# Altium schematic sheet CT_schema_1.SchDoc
size 543 x 488 mm
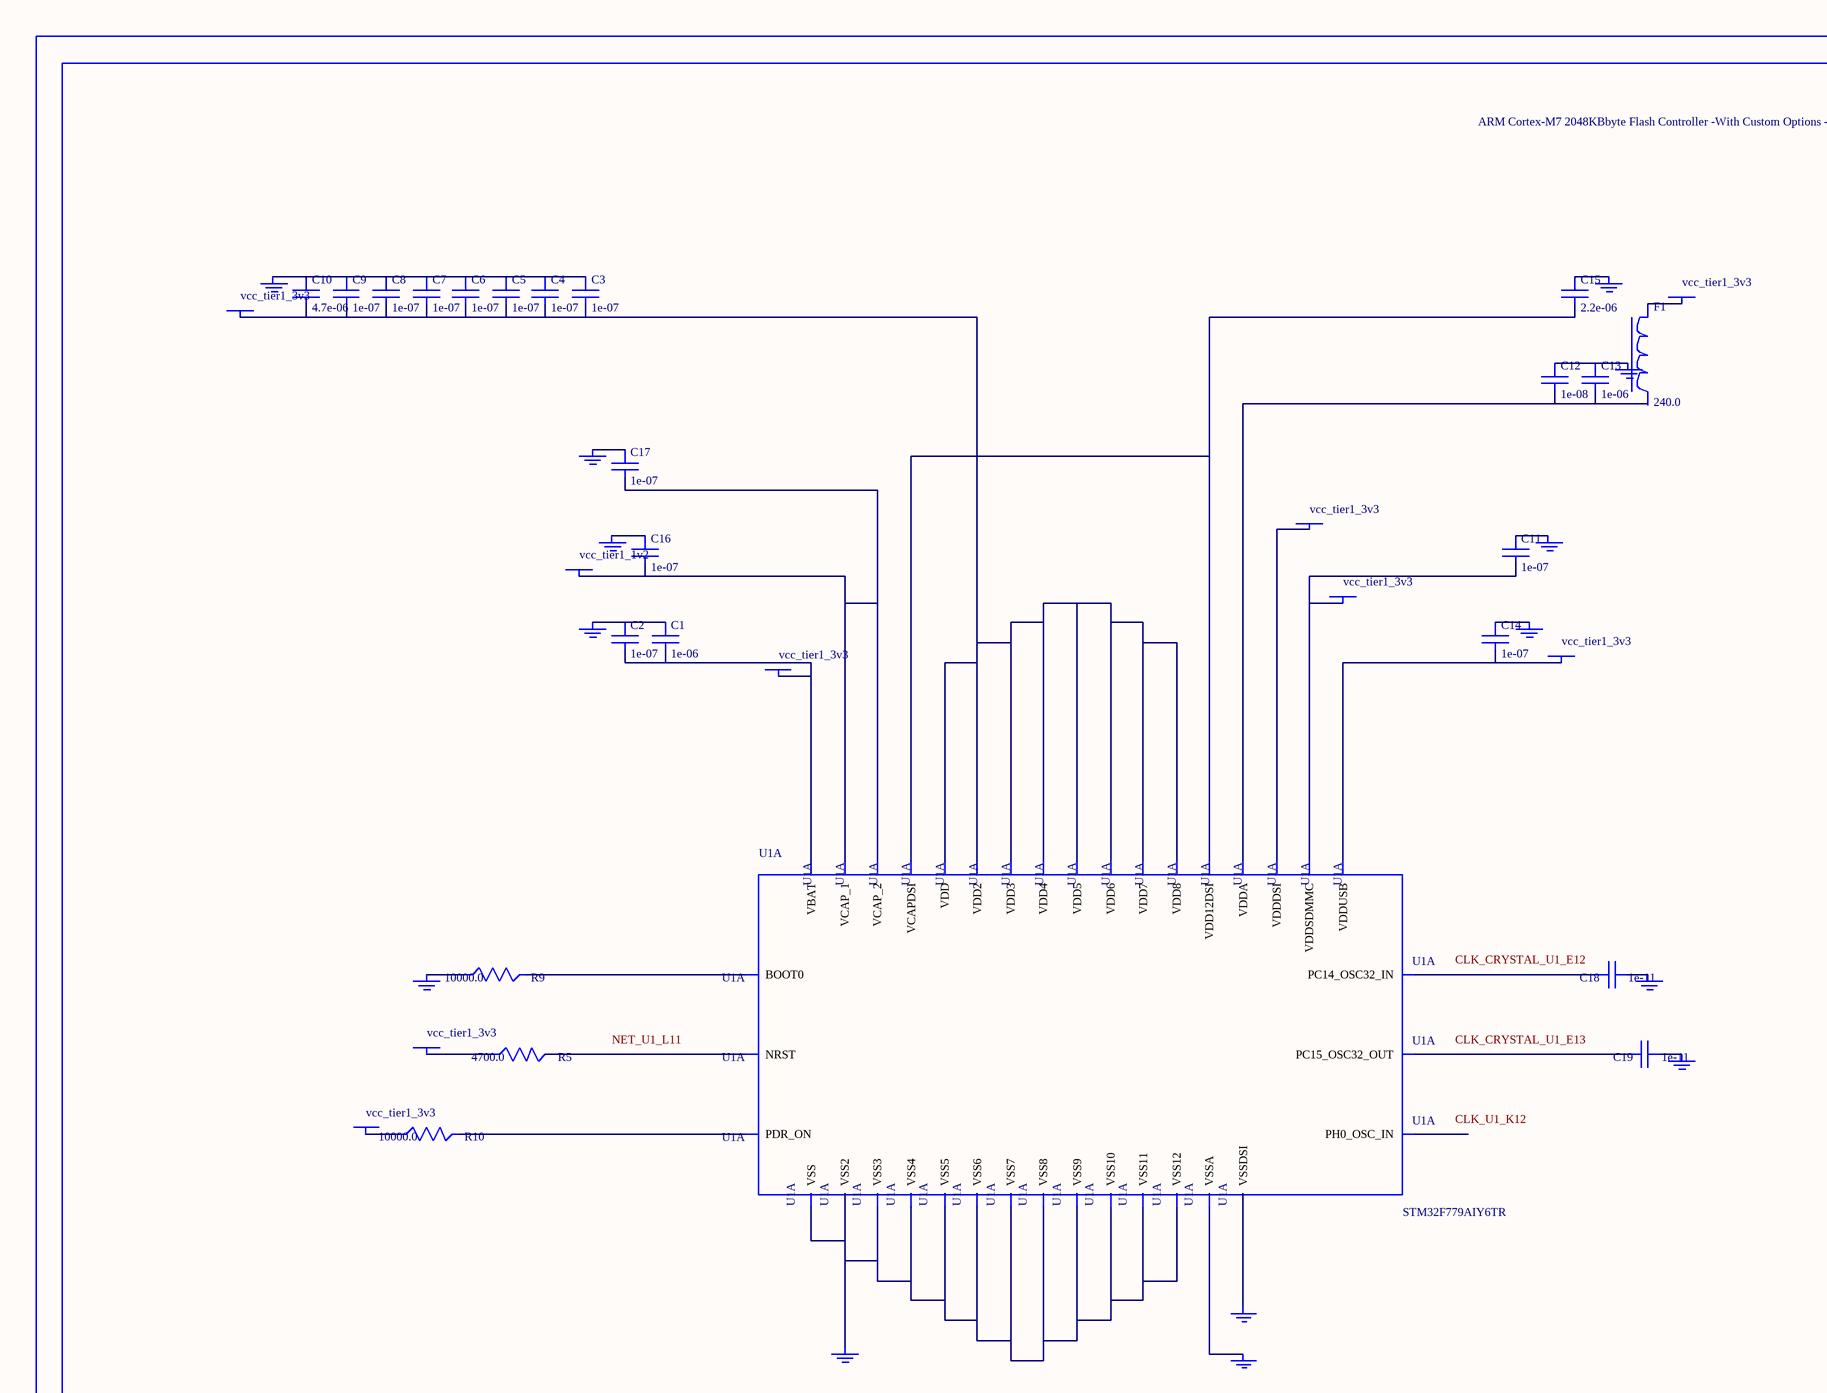
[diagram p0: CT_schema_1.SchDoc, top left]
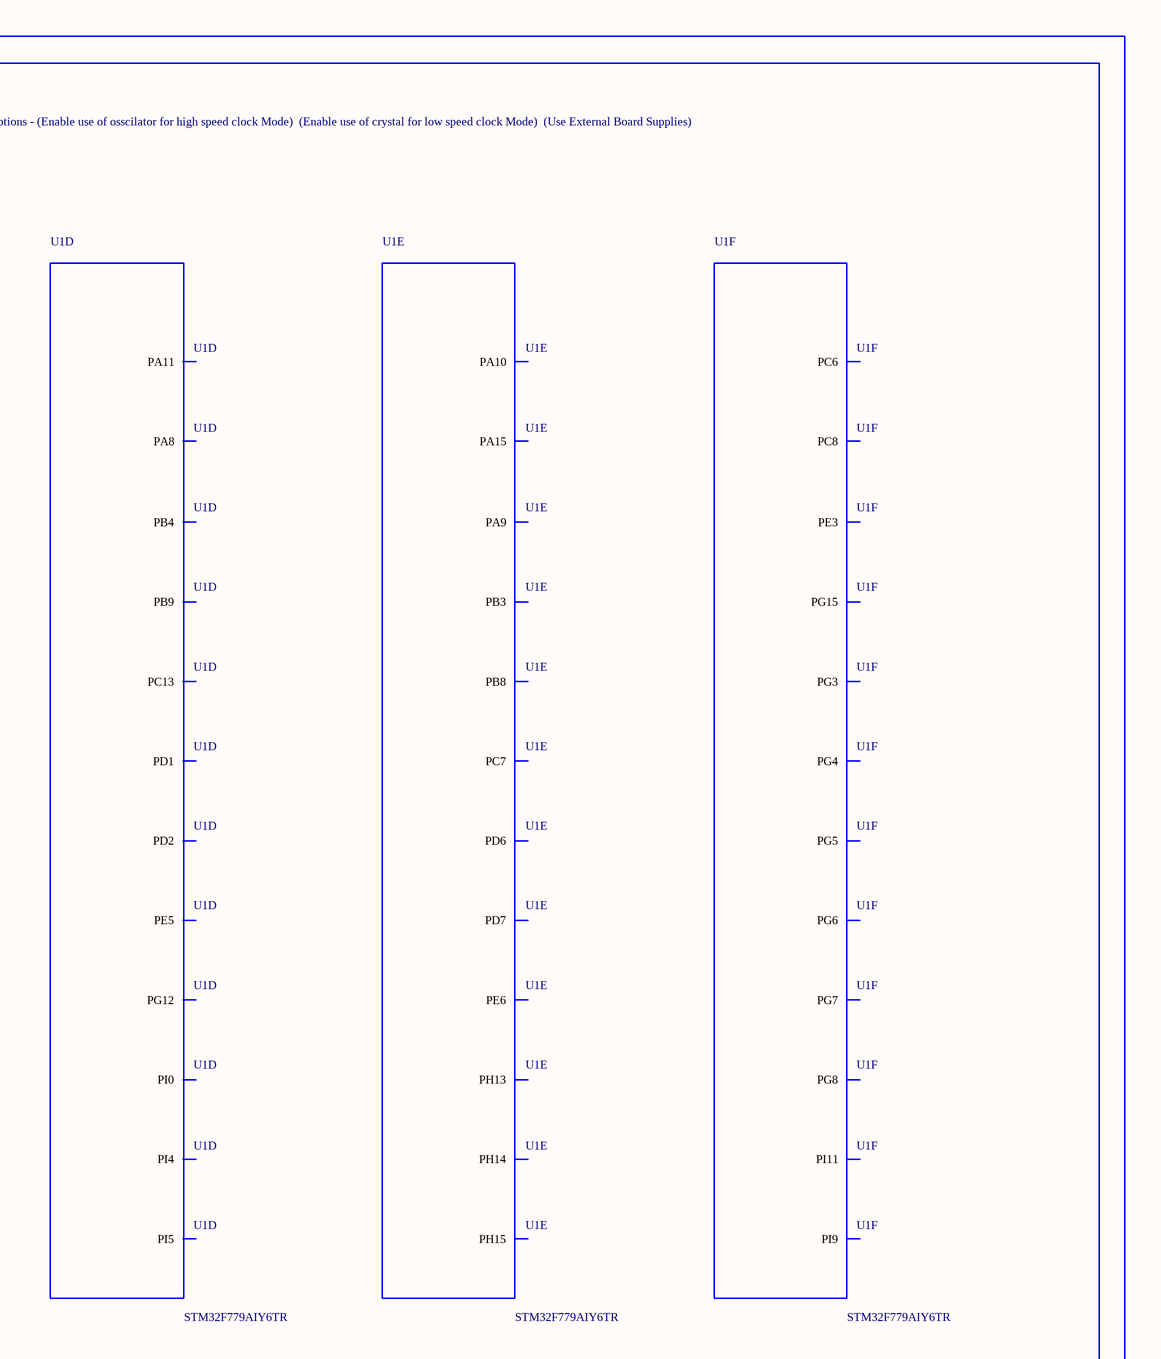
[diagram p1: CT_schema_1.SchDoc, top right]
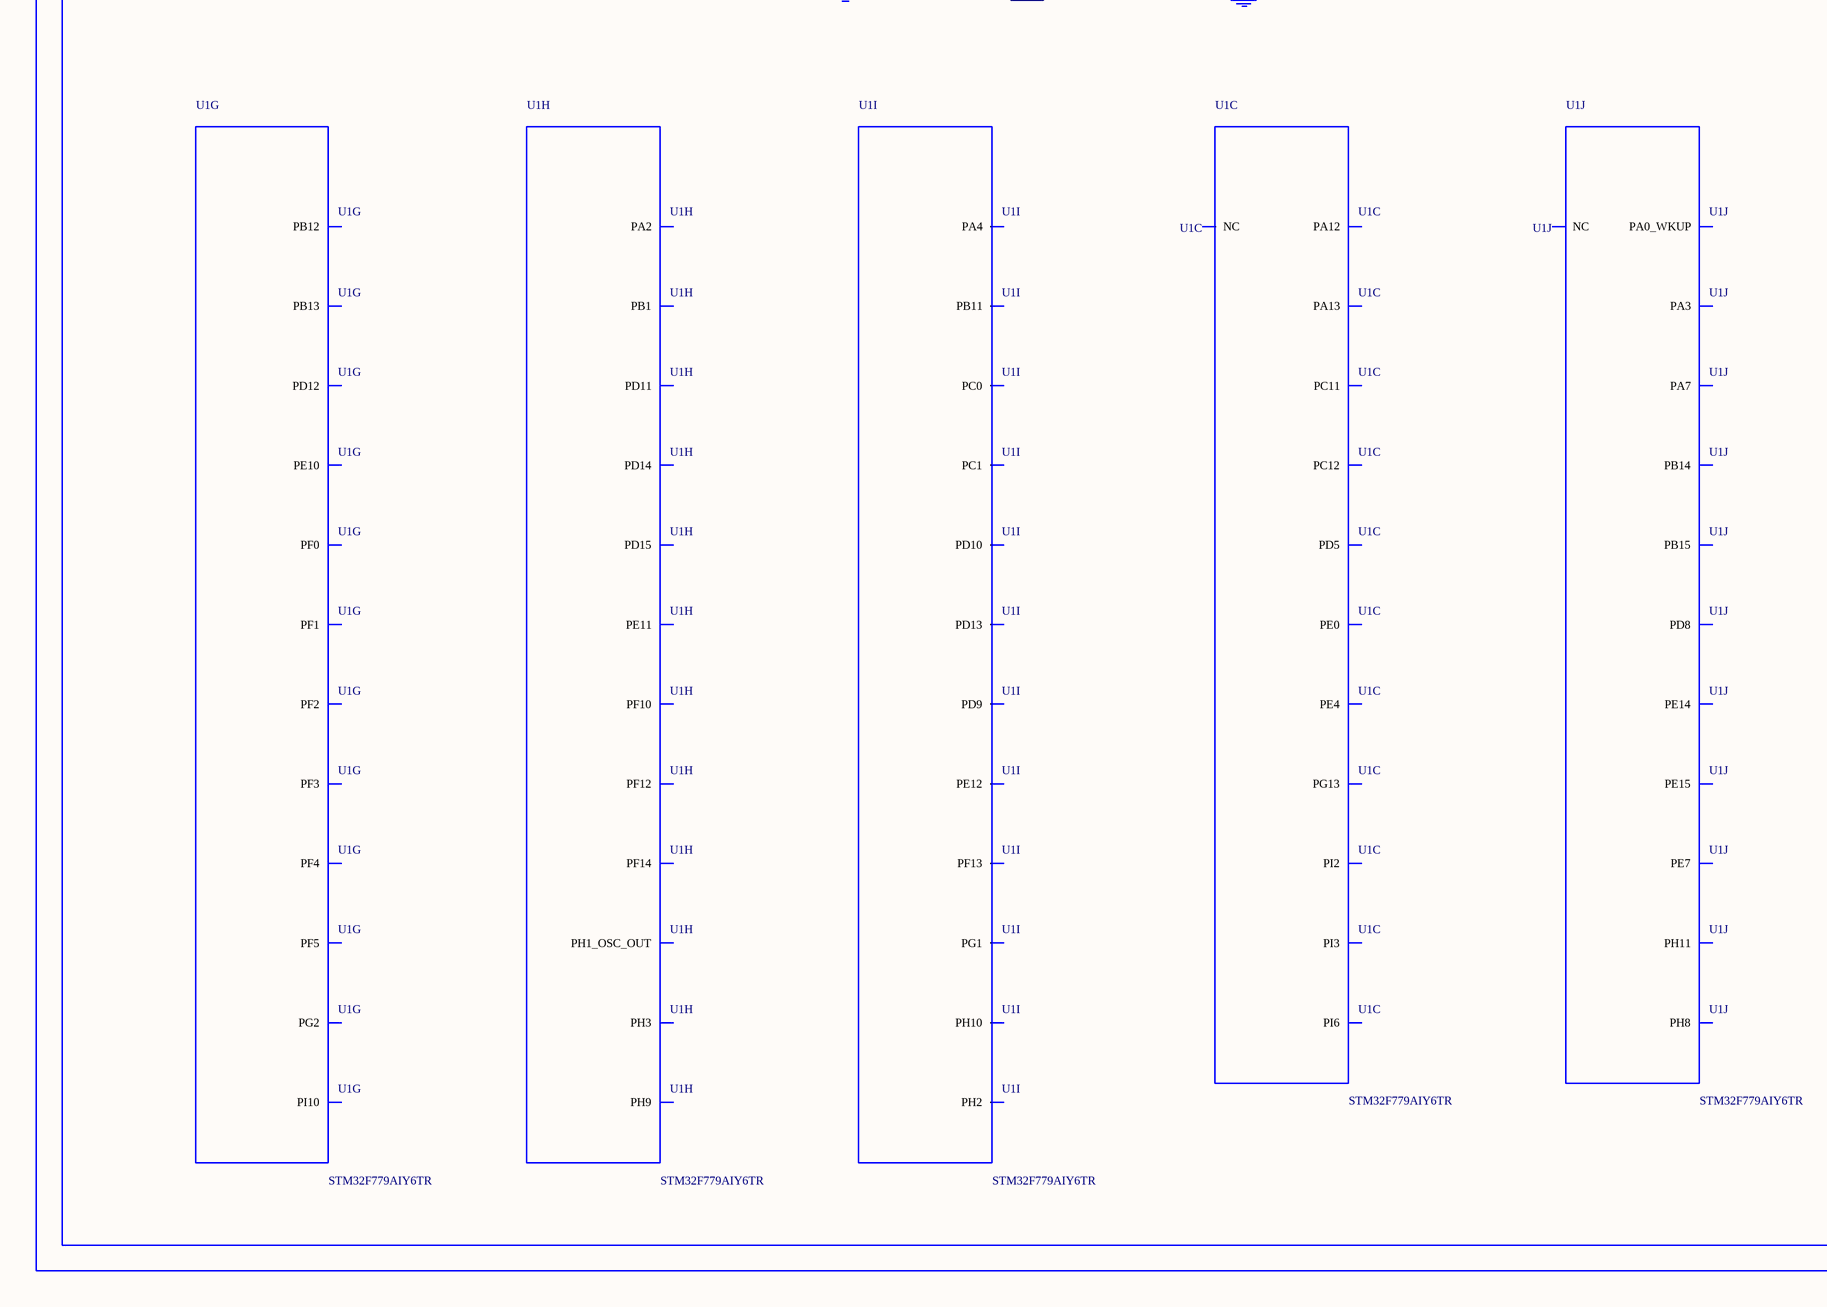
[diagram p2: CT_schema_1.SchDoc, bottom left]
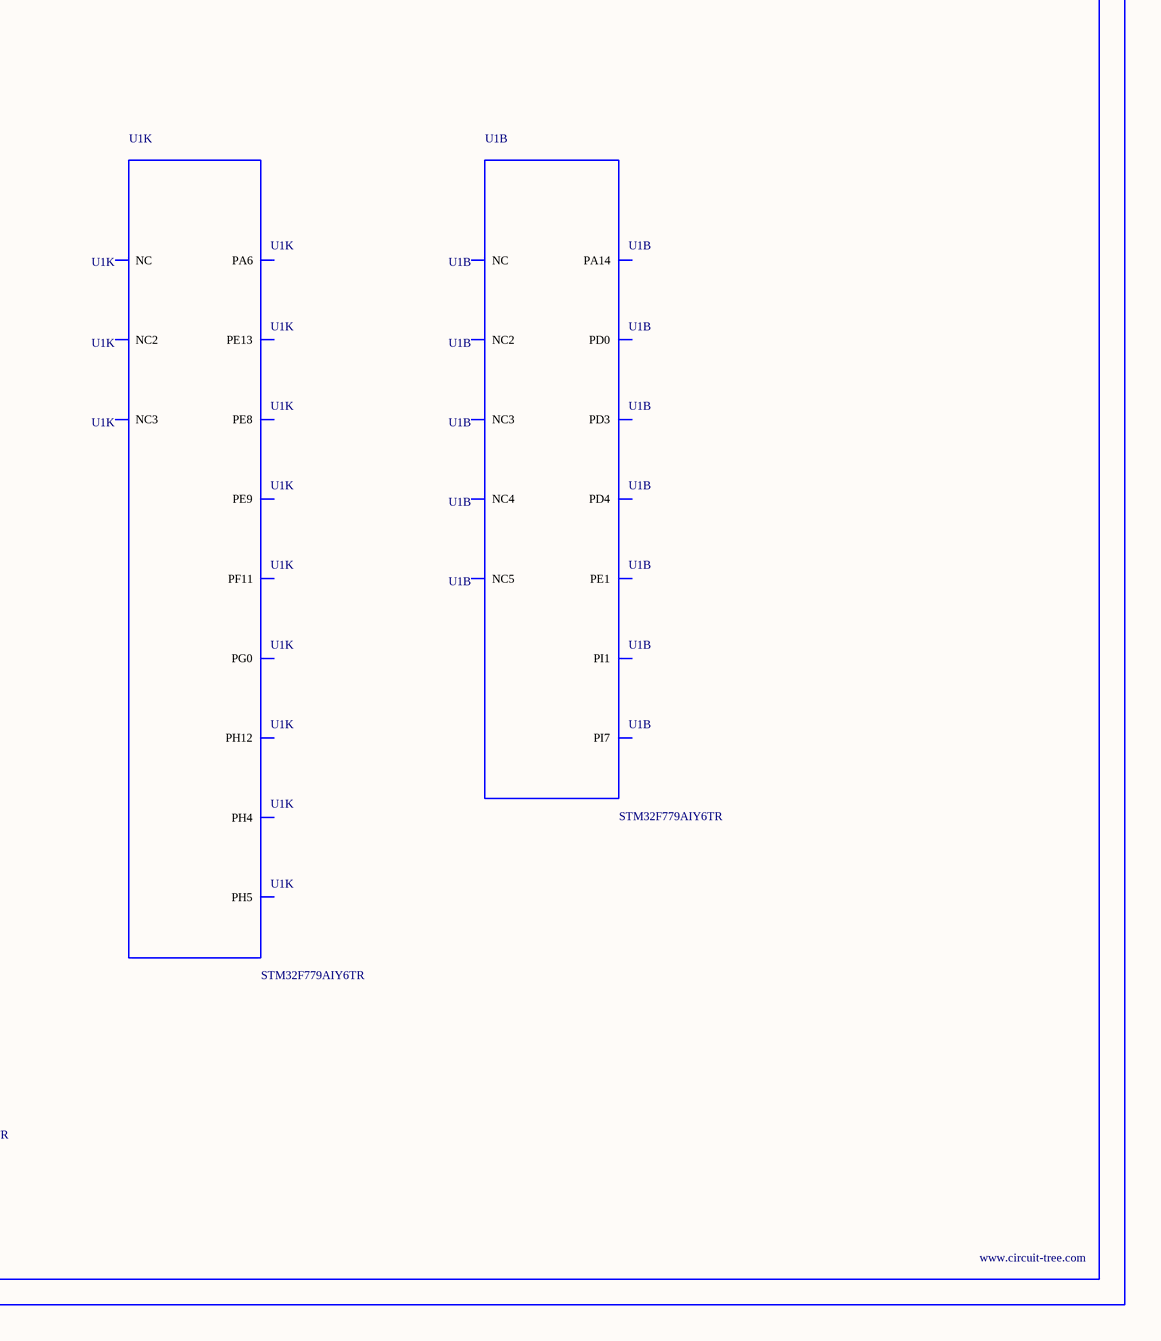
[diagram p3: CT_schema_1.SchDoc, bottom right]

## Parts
BORDER0  (no value)
C1  1e-06  [C0603]
C2  1e-07  [C0603]
C3  1e-07  [C0603]
C4  1e-07  [C0603]
C5  1e-07  [C0603]
C6  1e-07  [C0603]
C7  1e-07  [C0603]
C8  1e-07  [C0603]
C9  1e-07  [C0603]
C10  4.7e-06  [C0603]
C11  1e-07  [C0603]
C12  1e-08  [C0603]
C13  1e-06  [C0603]
C14  1e-07  [C0603]
C15  2.2e-06  [C0603]
C16  1e-07  [C0603]
C17  1e-07  [C0603]
C18  1e-11  [C0402]
C19  1e-11  [C0402]
F1  240.0  [L0603]
GND_INSTANCE_0_0  (no value)
GND_INSTANCE_0_1  (no value)
GND_INSTANCE_0_2  (no value)
GND_INSTANCE_0_3  (no value)
GND_INSTANCE_0_4  (no value)
GND_INSTANCE_0_5  (no value)
GND_INSTANCE_0_6  (no value)
GND_INSTANCE_0_7  (no value)
GND_INSTANCE_0_8  (no value)
GND_INSTANCE_0_9  (no value)
GND_INSTANCE_0_10  (no value)
GND_INSTANCE_0_11  (no value)
GND_INSTANCE_0_12  (no value)
GND_INSTANCE_0_13  (no value)
POWER_INSTANCE_0_0  vcc_tier1_3v3
POWER_INSTANCE_0_1  vcc_tier1_3v3
POWER_INSTANCE_0_2  vcc_tier1_3v3
POWER_INSTANCE_0_3  vcc_tier1_3v3
POWER_INSTANCE_0_4  vcc_tier1_3v3
POWER_INSTANCE_0_5  vcc_tier1_3v3
POWER_INSTANCE_0_6  vcc_tier1_1v2
POWER_INSTANCE_0_7  vcc_tier1_3v3
POWER_INSTANCE_0_8  vcc_tier1_3v3
R5  4700.0  [R0603]
R9  10000.0  [R0603]
R10  10000.0  [R0603]
U1  STM32F779AIY6TR  [WLCSP180]  (parts A,B,C,D,E,F,G,H,I,J,K of 15)

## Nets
NetC1_1: C1.1 C2.1 GND_INSTANCE_0_0.0(GND)
NetC1_2: C1.2 C2.2 POWER_INSTANCE_0_0.0(PWR) U1.C13(VBAT)
NetC3_1: C3.1 C4.1 C5.1 C6.1 C7.1 C8.1 C9.1 C10.1 GND_INSTANCE_0_2.0(GND)
NetC3_2: C3.2 C4.2 C5.2 C6.2 C7.2 C8.2 C9.2 C10.2 POWER_INSTANCE_0_2.0(PWR) U1.B2(VDD2) U1.B8(VDD3) U1.B11(VDD) U1.F12(VDD4) U1.J12(VDD5) U1.K9(VDD6) U1.M8(VDD7) U1.P4(VDD8)
NetC11_1: C11.1 GND_INSTANCE_0_4.0(GND)
NetC11_2: C11.2 POWER_INSTANCE_0_3.0(PWR) U1.A6(VDDSDMMC)
NetC12_1: C12.1 C13.1 GND_INSTANCE_0_1.0(GND)
NetC12_2: C12.2 C13.2 U1.M12(VDDA)
NetC14_1: C14.1 GND_INSTANCE_0_5.0(GND)
NetC14_2: C14.2 POWER_INSTANCE_0_5.0(PWR) U1.F2(VDDUSB)
NetC15_1: C15.1 GND_INSTANCE_0_6.0(GND)
NetC15_2: C15.2 U1.H6(VCAPDSI) U1.J3(VDD12DSI)
NetC16_1: C16.1 GND_INSTANCE_0_7.0(GND)
NetC16_2: C16.2 C17.2 POWER_INSTANCE_0_6.0(PWR) U1.C1(VCAP_2) U1.P5(VCAP_1)
NetC17_1: C17.1 GND_INSTANCE_0_8.0(GND)
NetC18_1: C18.1 GND_INSTANCE_0_9.0(GND)
NetC18_2: C18.2 U1.E12(PC14_OSC32_IN)
NetC19_1: C19.1 GND_INSTANCE_0_10.0(GND)
NetC19_2: C19.2 U1.E13(PC15_OSC32_OUT)
NetF1_1: F1.1 POWER_INSTANCE_0_1.0(PWR)
NetGND_INSTANCE_0_3_0: GND_INSTANCE_0_3.0(GND) R9.1
NetGND_INSTANCE_0_11_0: GND_INSTANCE_0_11.0(GND) U1.M11(VSSA)
NetGND_INSTANCE_0_12_0: GND_INSTANCE_0_12.0(GND) U1.A8(VSS2) U1.A11(VSS) U1.B6(VSS3) U1.C2(VSS4) U1.F1(VSS5) U1.F13(VSS6) U1.J9(VSS8) U1.J13(VSS7) U1.M1(VSS9) U1.N4(VSS10) U1.N5(VSS11) U1.P9(VSS12)
NetGND_INSTANCE_0_13_0: GND_INSTANCE_0_13.0(GND) U1.H5(VSSDSI)
NetPOWER_INSTANCE_0_4_0: POWER_INSTANCE_0_4.0(PWR) R10.1
NetPOWER_INSTANCE_0_7_0: POWER_INSTANCE_0_7.0(PWR) U1.K1(VDDDSI)
NetPOWER_INSTANCE_0_8_0: POWER_INSTANCE_0_8.0(PWR) R5.1
NetR5_2: R5.2 U1.L11(NRST)
NetR9_2: R9.2 U1.A10(BOOT0)
NetR10_2: R10.2 U1.C10(PDR_ON)

Not connected (* = marked no-connect by the designer): F1 2; U1 A1(NC) A2(NC4) A3(PA14) A4(PD0) A5(PD4) A12(NC2) A13(NC3) B1(NC5) B3(PI1) B5(PD3) B10(PE1) B12(PI7) B13(NC) C3(PI2) C4(PC11) C5(PD5) C7(PG13) C9(PE0) C11(PI6) C12(PE4) D1(PA12) D2(PA13) D3(PI3) D4(PC12) D5(PD1) D6(PD2) D7(PG12) D8(PB4) D9(PB9) D10(PI4) D11(PI5) D12(PE5) D13(PC13) E2(PA8) E3(PA11) E4(PI0) E5(PH15) E6(PD6) E7(PD7) E8(PB3) E9(PB8) E11(PE6) F3(PC7) F4(PA9) F5(PA10) F6(PH13) F7(PH14) F8(PA15) F9(PG15) F10(PE3) F11(PI11) G1(PG4) G2(PG5) G3(PG6) G4(PG7) G5(PG8) G6(PC6) G8(PC8) G9(PG3) G10(PI9) G11(PF0) G12(PF1) G13(PF2) H8(PB12) H9(PG2) H10(PI10) H11(PF3) H12(PF4) H13(PF5) J4(PD12) J5(PB13) J6(PE10) J8(PB1) J10(PA2) K2(PD15) K3(PD11) K4(PH9) K6(PE11) K7(PF12) K8(PF14) K10(PH3) K11(PF10) K12(PH0_OSC_IN) K13(PH1_OSC_OUT) L1(PD14) L2(PD13) L3(PD9) L4(PH10) L5(PB11) L6(PE12) L7(PG1) L8(PF13) L9(PA4) L10(PH2) L12(PC0) L13(PC1) M2(PD10) M3(PD8) M4(PH11) M5(PH8) M6(PE15) M7(PE7) M9(PA7) M10(PA3) M13(PA0_WKUP) N1(NC) N2(PB15) N3(PB14) N6(PE14) N7(PE8) N8(PG0) N9(PF11) N10(PA6) N11(PH5) N12(PH4) N13(NC) P1(NC2) P2(NC3) P3(PH12) P6(PE13) P7(PE9)

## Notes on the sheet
- Labels drawn without touching a wire or pin: CLK_CRYSTAL_U1_E12, CLK_CRYSTAL_U1_E13, CLK_U1_K12, NET_U1_L11

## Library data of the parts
BORDER0 = BORDER_PAGE0
C1 C13 = C0603C105K3RACTU
C2-C9 C11 C14 C16 C17 = 06035C104K4Z2A
C10 = GRM188R6YA475KE15D
C12 = 06035C103K4Z2A
C15 = C0603C225K8RACTU
C18 C19 = C0402C100K3GACTU
F1 = Z0603C241ASMST
GND_INSTANCE_0_0-GND_INSTANCE_0_13 = GND
POWER_INSTANCE_0_0-POWER_INSTANCE_0_8 = PWR
R5 = RC0603JR-074K7L
R9 R10 = RC0603JR-0710KL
